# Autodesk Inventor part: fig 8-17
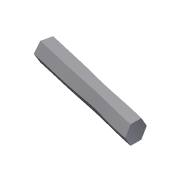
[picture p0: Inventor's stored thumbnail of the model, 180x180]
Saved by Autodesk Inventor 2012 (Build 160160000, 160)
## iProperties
Created: 2004-05
Part Number: fig 8-17
Document SubType Name: Modeling
Designer: CADCIM Technologies
Manufacturer: Standard
Standards Organization: Custom
Density: 1 g/cm^3
Material: Default
Author: CADCIM Technologies
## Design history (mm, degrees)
workplane "Work Plane2"
sketch "Sketch7"
  geometry: L1 (-42.583, 6.068)-(-42.583, 0.37) reference; 5 further points
  constraints: 1 point on line, 5 other
sketch "Sketch8"
  geometry: L1 (-42.583, 3.219)-(-107.269, 18.236); L2 (-42.583, 6.068)-(-42.583, 0.37) reference
  constraints: 2 end point, 1 midpoint
sweep "Sweep7" sketch "Sketch7", "Sketch8" dims "d6" = 0
body "Solid1"
sketch "Sketch2"
  geometry: L1 (-5.697, 0)-(-2.849, 4.934); L2 (-2.849, 4.934)-(2.849, 4.934); L3 (2.849, 4.934)-(5.697, 0); L4 (5.697, 0)-(2.849, -4.934); L5 (2.849, -4.934)-(-2.849, -4.934); L6 (-2.849, -4.934)-(-5.697, 0); 2 further points
  constraints: 12 end point, 1 coincident, 12 other
